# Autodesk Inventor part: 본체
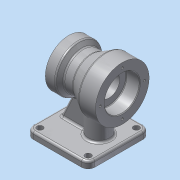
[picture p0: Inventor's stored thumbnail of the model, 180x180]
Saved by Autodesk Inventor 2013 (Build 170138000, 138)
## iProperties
Created: 2019-01
Part Number: 본체
Material: 알루미늄 6061
Document SubType Name: Modeling
Designer: Administrator
Density: 2.71 g/cm^3
Mass: 902.316 g
Surface Area: 601.686 cm^2
Volume: 332.958 cm^3
Author: Administrator
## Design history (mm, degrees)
sketch "스케치1"
  geometry: L1 (46, 46)-(-46, 46); L2 (-46, 46)-(-46, -46); L3 (-46, -46)-(46, -46); L4 (46, -46)-(46, 46); L5 (46, 46)-(-46, -46); L6 (-46, 46)-(46, -46); 1 further point
  constraints: 12 end point, 2 midpoint, 2 parallel, 1 horizontal, 1 perpendicular
  dimensions: "d0" = 92 distance of L1.start L1.end; "d2" = 92 distance of L3.end L1.start
extrude "돌출1" new body sketch "스케치1" distance "d3" = 10; taper "d4" = 0 deg
sketch "스케치2"
  geometry: L1 (-77.092, 80)-(63.387, 80); L2 (-51, 80)-(-51, 120); L3 (-51, 120)-(-26, 120); L4 (-26, 120)-(-5.215, 108); L5 (-5.215, 108)-(8.126, 108); L6 (8.126, 108)-(14, 115); L7 (14, 115)-(29, 115); L8 (29, 115)-(29, 80); L9 (-46, 0)-(-46, 10) reference; 1 further point
  constraints: 16 end point, 3 perpendicular, 2 parallel, 2 point on line, 1 horizontal
  dimensions: "d5" = 80 vertical distance of point (0, 0) L1.start; "d6" = 5 distance between parallel lines of L9 L2; "d7" = 25 distance of L2.end L3.end; "d8" = 15 distance of L6.end L7.end; "d9" = 80 diameter of L3 L1; "d10" = 70 diameter of L7 L1; "d11" = 30 deg angle of L5 L4; "d12" = 50 deg angle of L5 L6; "d13" = 56 diameter of L5 L1; "d14" = 80 distance between parallel lines of L8 L2
revolve "회전1" sketch "스케치2" stored, may be unused: angle "d15" = 90 deg
sketch "스케치3"
  geometry: L1 (46, 46)-(-46, 46) reference; L2 (46, -46)-(46, 46) reference; C1 r 16 at (16, 0); 1 further point
  constraints: 1 centre point
  dimensions: "d16" = 32 diameter of C1; "d18" = 30 distance from line of C1.centre L2; "d19" = 46 distance from line of C1.centre L1
extrude "돌출2" join sketch "스케치3" stored distance "d20" = 10; taper "d21" = 0 deg
sketch "스케치4"
  geometry: L1 (0, 10)-(0, 52) reference; L2 (46, 10)-(-46, 10) reference; L3 (8.126, 52)-(14, 45) reference; L4 (0, 52)-(8.126, 52) reference; L5 (19.679, 45)-(36, 10); L6 (36, 10)-(0, 10); L7 (46, 0)-(46, 10) reference; L8 (14, 45)-(29, 45) reference; 1 further point
  constraints: 4 end point, 2 point on line, 1 collinear
  dimensions: "d22" = 25 deg angle of L7 L5; "d23" = 10 distance from line of L7 L5.end
feature "리브1" sketch "스케치4" dims "d24" = 1, "d25" = 10, "d26" = 0, "d27" = 0, "d28" = 1, "d29" = 1
sketch "스케치5"
  geometry: L1 (-51, 40)-(-51, 120) reference; L2 (-74.237, 80)-(66.433, 80); L3 (-51, 106)-(-31, 106); L4 (-31, 106)-(-31, 96); L5 (-31, 96)-(12, 96); L6 (12, 96)-(12, 100); L7 (29, 45)-(29, 115) reference; L8 (12, 100)-(29, 100); L9 (29, 100)-(29, 80); L10 (29, 80)-(-51, 80); L11 (-51, 80)-(-51, 106); 1 further point
  constraints: 18 end point, 3 parallel, 3 perpendicular, 3 point on line, 2 midpoint, 1 collinear
  dimensions: "d30" = 80 vertical distance of L2.end point (0, 0); "d31" = 20 distance of L3.start L3.end; "d32" = 17 distance of L6.end L8.end; "d33" = 52 diameter of L3 L2; "d34" = 40 diameter of L8 L2; "d35" = 32 diameter of L5 L2
revolve "회전2" sketch "스케치5" stored, may be unused: angle "d36" = 90 deg
fillet "모깎기1" dims "d37" = 10
fillet "모깎기2" dims "d38" = 3
sketch "스케치6"
  geometry: C1 r 4.5 at (-36, 36); C2 r 4.5 at (36, 36); C3 r 4.5 at (36, -36); C4 r 4.5 at (-36, -36); A1 r 7 centre (-36, 36) between (-36, 43) and (-43, 36) reference; A2 r 7 centre (-36, -36) between (-43, -36) and (-36, -43) reference; A3 r 7 centre (36, -36) between (36, -43) and (43, -36) reference; A4 r 7 centre (36, 36) between (43, 36) and (36, 43) reference; 1 further point
  constraints: 4 centre point, 4 coincident, 3 equal radius
  dimensions: "d39" = 9 diameter of C1
extrude "돌출3" cut sketch "스케치6" distance "d41" = 10; taper "d42" = 0 deg
sketch "스케치7" dims "d43" = 66
  geometry: C1 r 26 at (0, 0) reference; 2 further points
  constraints: 2 horizontal alignment, 2 other
hole "구멍1" sketch "스케치7" at (-33, 0) diameter "d45" = 3.242; stored, may be unused: countersink angle "d49" = 90 deg, drill point angle "d51" = 118 deg; dims "d46" = 9, "d47" = 4, "d48" = 2, "d50" = 11
sketch "스케치8" dims "d55" = 55
  geometry: C1 r 20 at (0, 0) reference; 2 further points
  constraints: 2 horizontal alignment, 2 other
hole "구멍2" sketch "스케치8" at (27.5, 0) diameter "d57" = 3.242; stored, may be unused: countersink angle "d61" = 90 deg, drill point angle "d63" = 118 deg; dims "d58" = 9, "d59" = 4, "d60" = 2, "d62" = 11
fillet "모깎기3" dims "d67" = 1
chamfer "모따기1" distance "d68" = 1; stored, may be unused: second distance "d69" = 2, angle "d70" = 45 deg
fillet "모깎기4" dims "d71" = 0.6
fillet "모깎기5" dims "d72" = 3
fillet "모깎기6" dims "d73" = 3
fillet "모깎기7" dims "d74" = 3
sketch "스케치9"
  geometry: L1 (72, 0)-(0, 0) reference; L2 (82, -7)-(82, 0) reference; 2 further points
  constraints: 1 other
  dimensions: "d75" = 4 distance from line of point (36, -4) L1; "d76" = 46 distance from line of point (36, -4) L2
feature "엠보싱1" sketch "스케치9" dims "d0" = 92, "d2" = 92, "d77" = 0.5, "d78" = 0
node "솔리드1"
pattern_circular "원형 패턴1" dims angle "d53" = 360 deg
pattern_circular "원형 패턴2" dims angle "d65" = 360 deg
